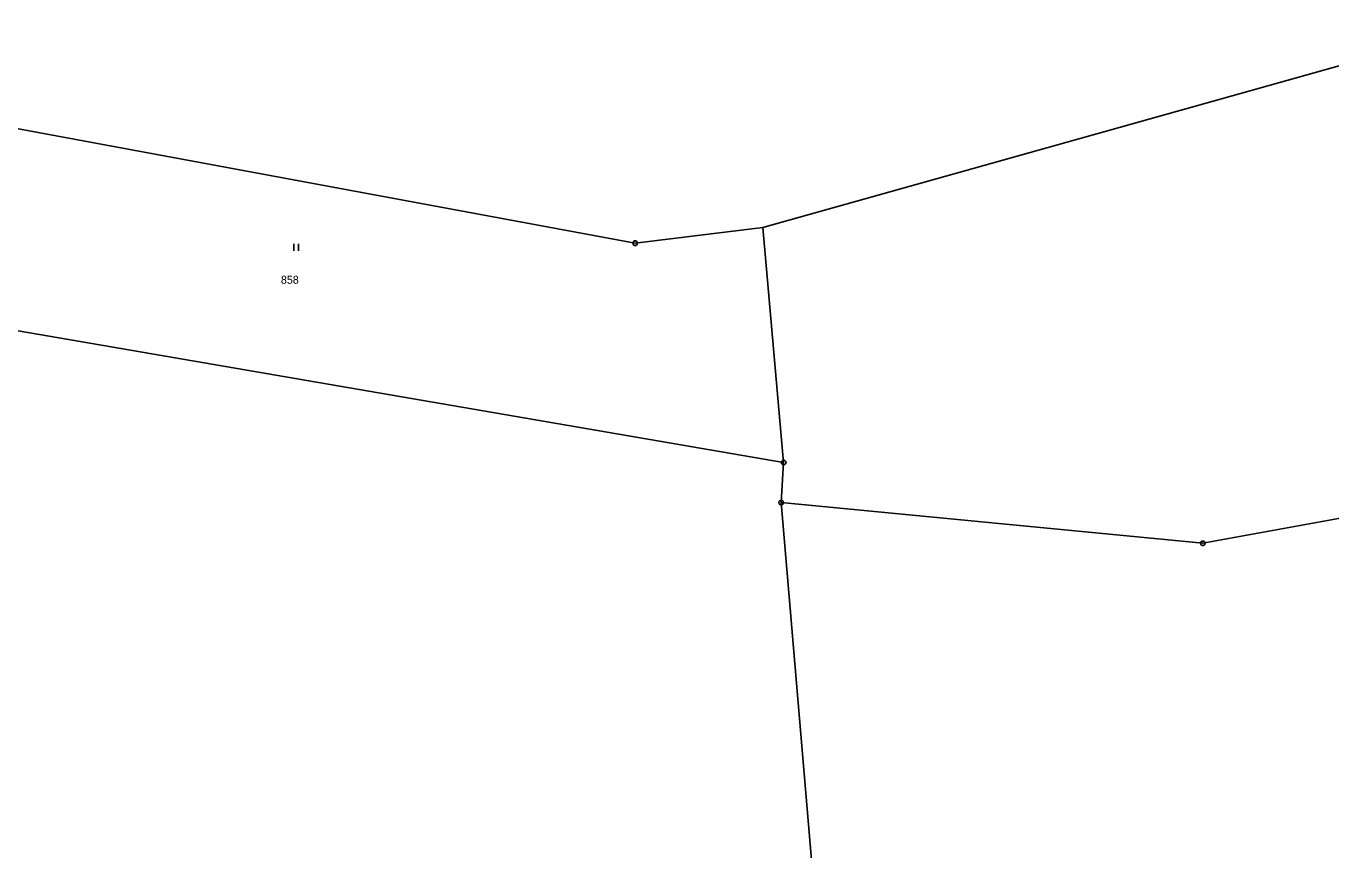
# Model space of a CAD drawing. Extents: x -871430 to -870620, y -1010094 to -1009649.
# Drawn here: x -870892.6 to -870823.3, y -1009775.5 to -1009731.8 of the extents above; entities that cross this region are included whole.
import ezdxf

# ---------------------------------------------------------------- set-up
doc = ezdxf.new("R2010")
doc.units = 0
for name, color, linetype in [('Vrstva 1', 7, 'Continuous'), ('Vrstva 2', 7, 'Continuous'), ('Vrstva 3', 7, 'Continuous'), ('Vrstva 8', 7, 'Continuous')]:
    doc.layers.add(name, color=color, linetype=linetype)

msp = doc.modelspace()

# ---------------------------------------------------------------- linework, layer by layer
at = {"layer": 'Vrstva 1'}
for p, q in [((-870780.52, -1009721.98), (-870853.46, -1009742.46)), ((-870860.24, -1009743.29), (-870901.37, -1009735.67)), ((-870853.46, -1009742.46), (-870860.24, -1009743.29)), ((-870852.35, -1009754.93), (-870853.46, -1009742.46)), ((-870852.35, -1009754.93), (-870903.98, -1009746.05)), ((-870852.48, -1009757.06), (-870852.35, -1009754.93)), ((-870810.65, -1009755.67), (-870830.08, -1009759.22)), ((-870830.08, -1009759.22), (-870852.48, -1009757.06)), ((-870849.95, -1009786.94), (-870852.48, -1009757.06))]:
    msp.add_line(p, q, dxfattribs=at)
at = {"layer": 'Vrstva 3'}
for p, q in [((-870878.375, -1009743.325), (-870878.375, -1009743.7)), ((-870878.125, -1009743.7), (-870878.125, -1009743.325))]:
    msp.add_line(p, q, dxfattribs=at)
at = {"layer": 'Vrstva 8'}
for p, q in [((-870860.252, -1009743.29), (-870860.228, -1009743.29)), ((-870852.362, -1009754.93), (-870852.338, -1009754.93)), ((-870852.492, -1009757.06), (-870852.468, -1009757.06)), ((-870830.092, -1009759.22), (-870830.068, -1009759.22))]:
    msp.add_line(p, q, dxfattribs=at)
for points in [[(-870860.202, -1009743.17), (-870860.14, -1009743.218), (-870860.115, -1009743.29), (-870860.14, -1009743.362), (-870860.202, -1009743.41), (-870860.278, -1009743.41), (-870860.34, -1009743.362), (-870860.365, -1009743.29), (-870860.34, -1009743.218), (-870860.278, -1009743.17), (-870860.202, -1009743.17)], [(-870852.312, -1009754.81), (-870852.25, -1009754.858), (-870852.225, -1009754.93), (-870852.25, -1009755.003), (-870852.312, -1009755.05), (-870852.388, -1009755.05), (-870852.45, -1009755.003), (-870852.475, -1009754.93), (-870852.45, -1009754.858), (-870852.388, -1009754.81), (-870852.312, -1009754.81)], [(-870852.442, -1009756.94), (-870852.38, -1009756.988), (-870852.355, -1009757.06), (-870852.38, -1009757.133), (-870852.442, -1009757.18), (-870852.518, -1009757.18), (-870852.58, -1009757.133), (-870852.605, -1009757.06), (-870852.58, -1009756.988), (-870852.518, -1009756.94), (-870852.442, -1009756.94)], [(-870830.042, -1009759.1), (-870829.98, -1009759.148), (-870829.955, -1009759.22), (-870829.98, -1009759.292), (-870830.042, -1009759.34), (-870830.117, -1009759.34), (-870830.18, -1009759.292), (-870830.205, -1009759.22), (-870830.18, -1009759.148), (-870830.117, -1009759.1), (-870830.042, -1009759.1)]]:
    msp.add_lwpolyline(points, dxfattribs=at)

# ---------------------------------------------------------------- texts
at = {"layer": 'Vrstva 2'}
msp.add_text('858', height=0.425, dxfattribs=at).set_placement((-870879.057, -1009745.442))

doc.saveas('drawing.dxf')
